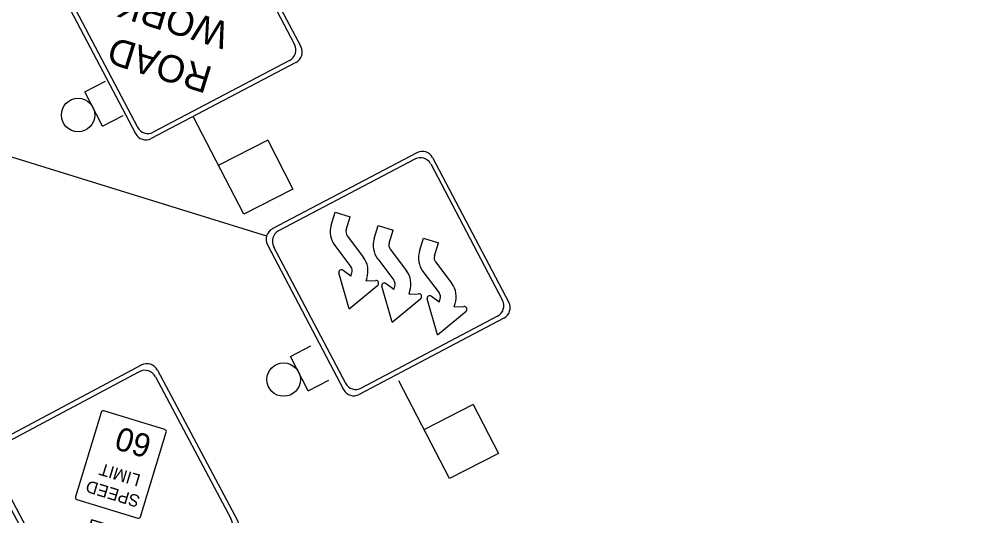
# Model space of a CAD drawing. Extents: x 2135767 to 2151731, y 141839 to 175894.
# Drawn here: x 2141647 to 2141895.8, y 170572.7 to 170700.1 of the extents above; entities that cross this region are included whole.
import ezdxf

# ---------------------------------------------------------------- set-up
doc = ezdxf.new("R2010")
doc.units = 0
for name, color, linetype in [('5', 7, 'Continuous'), ('Default', 7, 'Continuous'), ('PR_Dimensions_Phase', 7, 'Continuous'), ('PR_Phasing_Detour_1', 7, 'Continuous'), ('PR_Traffic_Control_Devices_Temp', 7, 'Continuous'), ('PR_Txt', 7, 'Continuous')]:
    doc.layers.add(name, color=color, linetype=linetype)

# ---------------------------------------------------------------- blocks, each defined once
blk = doc.blocks.new('W3-5')
at = {"layer": '5'}
for p, q in [((0.808, 7.633), (6.735, 13.56)), ((13.56, 7.633), (7.633, 13.56)), ((6.735, 0.808), (0.808, 6.735)), ((7.633, 0.808), (13.56, 6.735))]:
    blk.add_line(p, q, dxfattribs=at)
for centre, start, end in [((7.184, 13.111), 45, 135), ((1.257, 7.184), 135, 225), ((13.111, 7.184), 315, 45), ((7.184, 1.257), 225, 315)]:
    blk.add_arc(centre, 0.635, start, end, dxfattribs=at)
at = {"layer": 'Default'}
for p, q in [((0.448, 7.633), (6.735, 13.919)), ((13.919, 7.633), (7.633, 13.919)), ((6.95, 12.723), (4.277, 10.304)), ((9.984, 10.322), (7.366, 12.687)), ((8.797, 8.13), (5.464, 8.13)), ((5.352, 8.019), (5.352, 3.415)), ((8.908, 3.415), (8.908, 8.019)), ((6.735, 0.449), (0.448, 6.735)), ((7.633, 0.449), (13.919, 6.735)), ((5.464, 3.304), (8.797, 3.304))]:
    blk.add_line(p, q, dxfattribs=at)
for points in [[(4.277, 10.304), (6.95, 12.723)], [(7.366, 12.687), (9.984, 10.322)], [(4.584, 9.924), (6.553, 10.412), (6.553, 8.913), (7.745, 8.913), (7.745, 10.448), (9.677, 9.96)], [(9.677, 9.96), (7.745, 10.448), (7.745, 8.913), (6.553, 8.913), (6.553, 10.412), (4.584, 9.924)]]:
    blk.add_lwpolyline(points, dxfattribs=at)
for centre, radius, start, end in [((7.184, 13.47), 0.635, 45, 135), ((7.141, 12.512), 0.285, 37.9142, 132.1493), ((7.141, 12.512), 0.285, 37.9142, 132.1493), ((4.519, 10.186), 0.269, 154.0903, 283.9085), ((4.519, 10.186), 0.269, 154.0903, 283.9085), ((9.825, 10.146), 0.237, 231.3417, 47.9123), ((9.825, 10.146), 0.237, 231.3417, 47.9123), ((5.464, 8.019), 0.111, 90, 180), ((8.797, 8.019), 0.111, 0, 90), ((0.897, 7.184), 0.635, 135, 225), ((13.47, 7.184), 0.635, 315, 45), ((5.464, 3.415), 0.111, 180, 270), ((8.797, 3.415), 0.111, 270, 0), ((7.184, 0.898), 0.635, 225, 315)]:
    blk.add_arc(centre, radius, start, end, dxfattribs=at)
for s, p in [('SPEED', (5.649, 6.987)), ('LIMIT', (5.945, 5.929))]:
    blk.add_text(s, height=0.635, dxfattribs=at).set_placement(p)
blk = doc.blocks.new('FLSHFLAG')
at = {"layer": 'PR_Txt'}
for p, q in [((-1.202, 14.125), (0.838, 16.147)), ((0.838, 16.147), (4.9, 12.085)), ((0.819, 12.085), (-1.202, 14.125)), ((0.819, 12.085), (2.86, 14.106)), ((9.258, 14.004), (8.403, 13.149)), ((9.258, 14.004), (10.685, 12.576)), ((10.685, 12.576), (9.831, 11.722))]:
    blk.add_line(p, q, dxfattribs=at)
blk.add_circle((10.653, 13.836), 0.873, dxfattribs=at)
blk = doc.blocks.new('Cw20-1_none')
at = {"layer": 'Default'}
for p, q in [((0.177, 3.005), (2.651, 5.48)), ((5.48, 3.005), (3.005, 5.48)), ((0.318, 3.005), (2.651, 5.339)), ((5.338, 3.005), (3.005, 5.339)), ((2.651, 0.177), (0.177, 2.652)), ((2.651, 0.318), (0.318, 2.652)), ((3.005, 0.177), (5.48, 2.652)), ((3.005, 0.318), (5.338, 2.652))]:
    blk.add_line(p, q, dxfattribs=at)
for centre, start, end in [((2.828, 5.303), 45, 135), ((2.828, 5.162), 45, 135), ((0.353, 2.828), 135, 225), ((0.495, 2.828), 135, 225), ((5.162, 2.828), 315, 45), ((5.303, 2.828), 315, 45), ((2.828, 0.495), 225, 315), ((2.828, 0.354), 225, 315)]:
    blk.add_arc(centre, 0.25, start, end, dxfattribs=at)
for s, p in [('ROAD', (1.821, 3.637)), ('WORK', (1.751, 2.623))]:
    blk.add_text(s, height=0.5833, dxfattribs=at).set_placement(p)

msp = doc.modelspace()

# ---------------------------------------------------------------- linework, layer by layer
at = {"layer": 'PR_Dimensions_Phase'}
msp.add_line((2141451.55, 170724.74), (2141710.53, 170644.49), dxfattribs=at)
at = {"layer": 'PR_Phasing_Detour_1'}
msp.add_circle((2140069.54, 171591.41), 4302.23, dxfattribs=at)
at = {"layer": 'PR_Traffic_Control_Devices_Temp'}
for p, q in [((2141749.16, 170665.83), (2141712, 170646.26)), ((2141748.65, 170664.21), (2141713.62, 170645.75)), ((2141753.21, 170664.58), (2141772.79, 170627.42)), ((2141752.71, 170662.96), (2141771.17, 170627.92)), ((2141727.14, 170647.25), (2141728.17, 170650.57)), ((2141728.17, 170650.57), (2141732.04, 170649.37)), ((2141731.01, 170646.04), (2141732.04, 170649.37)), ((2141738.17, 170643.82), (2141739.2, 170647.15)), ((2141738.17, 170643.82), (2141739.2, 170647.15)), ((2141738.17, 170643.82), (2141739.2, 170647.15)), ((2141739.2, 170647.15), (2141743.08, 170645.95)), ((2141739.2, 170647.15), (2141743.08, 170645.95)), ((2141739.2, 170647.15), (2141743.08, 170645.95)), ((2141731.29, 170644.48), (2141735.44, 170638.98)), ((2141742.05, 170642.62), (2141743.08, 170645.95)), ((2141742.05, 170642.62), (2141743.08, 170645.95)), ((2141742.05, 170642.62), (2141743.08, 170645.95)), ((2141710.74, 170642.2), (2141730.32, 170605.05)), ((2141712.36, 170641.7), (2141730.82, 170606.67)), ((2141728.05, 170642.03), (2141732.2, 170636.53)), ((2141749.82, 170640.57), (2141750.85, 170643.89)), ((2141750.85, 170643.89), (2141754.73, 170642.69)), ((2141753.7, 170639.37), (2141754.73, 170642.69)), ((2141754.73, 170642.69), (2141754.73, 170642.69)), ((2141754.73, 170642.69), (2141754.73, 170642.69)), ((2141754.73, 170642.69), (2141754.73, 170642.69)), ((2141754.73, 170642.69), (2141754.73, 170642.69)), ((2141742.33, 170641.06), (2141746.48, 170635.55)), ((2141742.33, 170641.06), (2141746.48, 170635.55)), ((2141742.33, 170641.06), (2141746.48, 170635.55)), ((2141739.09, 170638.61), (2141743.24, 170633.11)), ((2141739.09, 170638.61), (2141743.24, 170633.11)), ((2141739.09, 170638.61), (2141743.24, 170633.11)), ((2141753.97, 170637.8), (2141758.13, 170632.3)), ((2141731.75, 170625.77), (2141729.1, 170634.97)), ((2141732.22, 170634.13), (2141730.23, 170635.62)), ((2141732.22, 170634.13), (2141732.48, 170634.97)), ((2141750.73, 170635.36), (2141754.89, 170629.85)), ((2141731.75, 170625.77), (2141739.14, 170631.86)), ((2141736.1, 170632.93), (2141736.35, 170633.76)), ((2141736.1, 170632.93), (2141738.58, 170633.03)), ((2141742.79, 170622.35), (2141740.14, 170631.55)), ((2141742.79, 170622.35), (2141740.14, 170631.55)), ((2141742.79, 170622.35), (2141740.14, 170631.55)), ((2141743.26, 170630.71), (2141741.27, 170632.2)), ((2141743.26, 170630.71), (2141741.27, 170632.2)), ((2141743.26, 170630.71), (2141741.27, 170632.2)), ((2141743.26, 170630.71), (2141743.52, 170631.55)), ((2141743.26, 170630.71), (2141743.52, 170631.55)), ((2141743.26, 170630.71), (2141743.52, 170631.55)), ((2141747.14, 170629.51), (2141747.39, 170630.34)), ((2141747.14, 170629.51), (2141747.39, 170630.34)), ((2141747.14, 170629.51), (2141747.39, 170630.34)), ((2141747.14, 170629.51), (2141749.61, 170629.61)), ((2141747.14, 170629.51), (2141749.61, 170629.61)), ((2141747.14, 170629.51), (2141749.61, 170629.61)), ((2141742.79, 170622.35), (2141750.18, 170628.44)), ((2141742.79, 170622.35), (2141750.18, 170628.44)), ((2141742.79, 170622.35), (2141750.18, 170628.44)), ((2141754.44, 170619.1), (2141751.79, 170628.29)), ((2141754.9, 170627.46), (2141752.91, 170628.94)), ((2141754.9, 170627.46), (2141755.16, 170628.29)), ((2141758.78, 170626.25), (2141759.04, 170627.09)), ((2141754.44, 170619.1), (2141761.82, 170625.19)), ((2141758.78, 170626.25), (2141761.26, 170626.35)), ((2141771.53, 170623.37), (2141734.37, 170603.79)), ((2141769.91, 170623.87), (2141734.88, 170605.41))]:
    msp.add_line(p, q, dxfattribs=at)
for centre, radius, start, end in [((2141750.05, 170661.56), 3, 27.7835, 117.7835), ((2141750.56, 170663.18), 3, 27.7835, 117.7835), ((2141732.68, 170645.53), 5.8, 162.7835, 217.0513), ((2141713.4, 170643.6), 3, 117.7835, 207.7835), ((2141715.02, 170643.1), 3, 117.7835, 207.7835), ((2141732.68, 170645.53), 1.74, 162.7835, 217.0513), ((2141743.71, 170642.11), 5.8, 162.7835, 217.0513), ((2141743.71, 170642.11), 5.8, 162.7835, 217.0513), ((2141743.71, 170642.11), 5.8, 162.7835, 217.0513), ((2141743.71, 170642.11), 1.74, 162.7835, 217.0513), ((2141743.71, 170642.11), 1.74, 162.7835, 217.0513), ((2141743.71, 170642.11), 1.74, 162.7835, 217.0513), ((2141730.81, 170635.48), 5.8, 342.7835, 37.0513), ((2141755.36, 170638.85), 5.8, 162.7835, 217.0513), ((2141755.36, 170638.85), 1.74, 162.7835, 217.0513), ((2141730.81, 170635.48), 1.74, 342.7835, 37.0513), ((2141729.78, 170635.09), 0.689, 49.6345, 201.9001), ((2141741.85, 170632.06), 5.8, 342.7835, 37.0513), ((2141741.85, 170632.06), 5.8, 342.7835, 37.0513), ((2141741.85, 170632.06), 5.8, 342.7835, 37.0513), ((2141738.65, 170632.35), 0.689, 303.6669, 95.9326), ((2141740.82, 170631.67), 0.689, 49.6345, 201.9001), ((2141740.82, 170631.67), 0.689, 49.6345, 201.9001), ((2141740.82, 170631.67), 0.689, 49.6345, 201.9001), ((2141741.85, 170632.06), 1.74, 342.7835, 37.0513), ((2141741.85, 170632.06), 1.74, 342.7835, 37.0513), ((2141741.85, 170632.06), 1.74, 342.7835, 37.0513), ((2141753.5, 170628.8), 5.8, 342.7835, 37.0513), ((2141749.69, 170628.92), 0.689, 303.6669, 95.9326), ((2141749.69, 170628.92), 0.689, 303.6669, 95.9326), ((2141749.69, 170628.92), 0.689, 303.6669, 95.9326), ((2141752.47, 170628.42), 0.689, 49.6345, 201.9001), ((2141753.5, 170628.81), 1.74, 342.7835, 37.0513), ((2141768.51, 170626.52), 3, 297.7835, 27.7835), ((2141770.13, 170626.02), 3, 297.7835, 27.7835), ((2141761.33, 170625.67), 0.689, 303.6669, 95.9326), ((2141733.48, 170608.07), 3, 207.7835, 297.7835), ((2141732.97, 170606.44), 3, 207.7835, 297.7835)]:
    msp.add_arc(centre, radius, start, end, dxfattribs=at)

# ---------------------------------------------------------------- block references
for name, p, xscale, yscale, rotation in [('Cw20-1_none', (2141730.82, 170722.84), 11.999999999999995, 11.999999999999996, 162.72081903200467), ('FLSHFLAG', (2141732.7, 170724.52), 4.921250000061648, 4.921250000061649, 162.35580171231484), ('W3-5', (2141714.87, 170602.45), 4.921250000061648, 4.921250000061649, 163.0193420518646), ('FLSHFLAG', (2141785.47, 170656.67), 4.921250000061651, 4.921250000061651, 162.41849638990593)]:
    msp.add_blockref(name, p, dxfattribs=dict(at, xscale=xscale, yscale=yscale, rotation=rotation))

# ---------------------------------------------------------------- texts
msp.add_text('60', height=6, rotation=163.3844, dxfattribs=at).set_placement((2141681.4, 170593.06))

doc.saveas('drawing.dxf')
